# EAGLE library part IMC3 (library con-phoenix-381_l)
Invertierter Mini-Combicon 3.81mm horizontal 3-polig IMC 1,5/3-G-3,81 (ohne Gegenstecker)
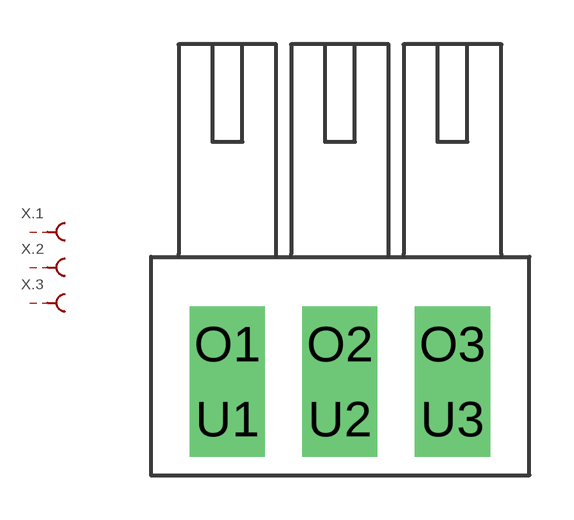
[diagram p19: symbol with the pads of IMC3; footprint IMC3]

Designator prefix X; gates .1=MCBU .2=MCBU .3=MCBU

## IMC3  [IMC3]
O1  .1:S  pas
O2  .2:S  pas
O3  .3:S  pas
U1  .1:SK  pas
U2  .2:SK  pas
U3  .3:SK  pas

## Footprint IMC3 (pad centres in mm)
Mini-Combicon 3.81mm horizontal 3-polig invertiert (ohne Gegenstecker)
drill 1.3 pad 2.54 square: O1 -3.81,1.27; O2 0,1.27; O3 3.81,1.27; U1 -3.81,-1.27; U2 0,-1.27; U3 3.81,-1.27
